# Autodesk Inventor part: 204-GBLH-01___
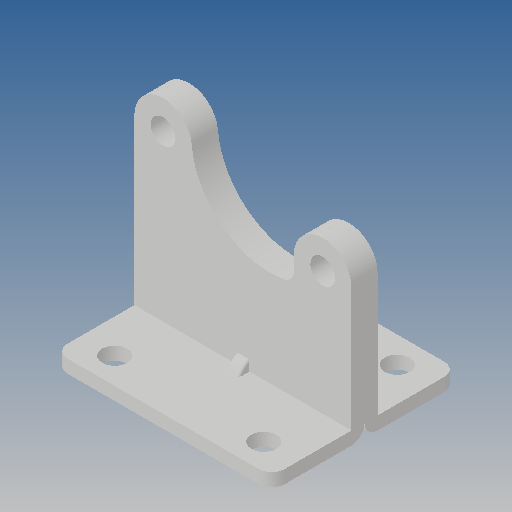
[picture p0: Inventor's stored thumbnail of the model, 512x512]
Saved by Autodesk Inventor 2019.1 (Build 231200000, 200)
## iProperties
Created: 2012-09
Part Number: 204-GBLH-01___
Material: Ogólny
Document SubType Name: Modeling
Designer: CADENGINEERING4
Density: 1 g/cm^3
Appearance: Domyślna
Author: CADENGINEERING4
Revision Number: ÈÎºÎ
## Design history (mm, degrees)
feature "NONE" [ÊäÈë]
feature "ÊäÈë2"
node "Bryła1"
node "Bryła2"
